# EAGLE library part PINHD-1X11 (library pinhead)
PIN HEADER
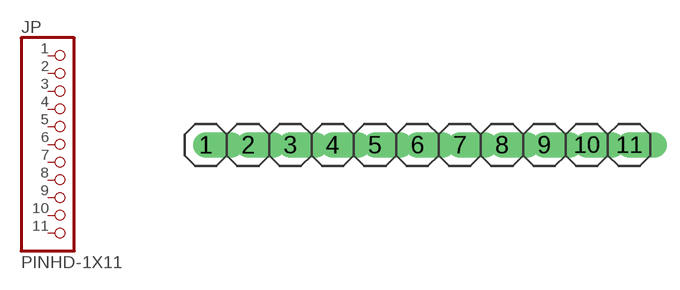
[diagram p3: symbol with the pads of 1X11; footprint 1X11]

Designator prefix JP

## PINHD-1X11  [1X11]
1  1  pas
2  2  pas
3  3  pas
4  4  pas
5  5  pas
6  6  pas
7  7  pas
8  8  pas
9  9  pas
10  10  pas
11  11  pas

## Footprint 1X11 (pad centres in mm)
PIN HEADER
drill 1.016 offset: 1 -12.7,0; 2 -10.16,0; 3 -7.62,0; 4 -5.08,0; 5 -2.54,0; 6 0,0; 7 2.54,0; 8 5.08,0; 9 7.62,0; 10 10.16,0; 11 12.7,0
